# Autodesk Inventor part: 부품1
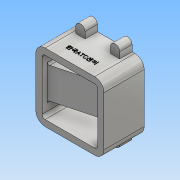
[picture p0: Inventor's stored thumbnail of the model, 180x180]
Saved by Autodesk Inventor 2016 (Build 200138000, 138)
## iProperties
Created: 2018-01
Part Number: 부품1
Material: 알루미늄 6061
Document SubType Name: Modeling
Designer: Administrator
Mass: 994.428 g
Surface Area: 845.509 cm^2
Volume: 368.307 cm^3
Density: 2.7 g/cm^3
Appearance: 알루미늄 - 평지
Author: Administrator
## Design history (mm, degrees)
sketch "스케치2"
  geometry: L1 (40, -55)-(-40, -55); L2 (-55, -40)-(-55, 40); L3 (-40, 55)-(40, 55); L4 (55, 40)-(55, -40); L5 (0, 55)-(0, -55); L6 (55, 0)-(-55, 0); A1 r 15 centre (40, -40) between (40, -55) and (55, -40); A2 r 15 centre (-40, -40) between (-55, -40) and (-40, -55); A3 r 15 centre (-40, 40) between (-40, 55) and (-55, 40); A4 r 15 centre (40, 40) between (55, 40) and (40, 55); 5 further points
  constraints: 12 end point, 8 point on circle, 8 tangent, 6 point on line, 5 midpoint, 4 centre point, 3 equal radius, 2 parallel, 1 coincident, 1 horizontal, 1 perpendicular
  dimensions: "d0" = 110 distance of point (-55, 55) point (55, 55); "d1" = 110 distance of point (-55, -55) point (-55, 55); "d2" = 15 radius of A1
extrude "돌출1" new body sketch "스케치2" distance "d3" = 65; taper "d4" = 0 deg
sketch "스케치3"
  geometry: L1 (40, 55)-(-40, 55) reference; L2 (-55, 40)-(-55, -40) reference; L3 (-35.5, 65)-(-35.5, 50.607); L4 (-35.5, 50.607)-(-20.5, 50.607); L5 (-20.5, 50.607)-(-20.5, 65); L6 (20.5, 65)-(20.5, 49.182); L7 (20.5, 49.182)-(35.5, 49.182); L8 (35.5, 49.182)-(35.5, 65); A1 r 7.5 centre (-28, 65) between (-20.5, 65) and (-35.5, 65); A2 r 7.5 centre (28, 65) between (35.5, 65) and (20.5, 65); 1 further point
  constraints: 12 end point, 4 point on circle, 2 centre point, 2 perpendicular, 2 tangent, 2 vertical
  dimensions: "d5" = 15 diameter of A1; "d6" = 15 diameter of A2; "d7" = 56 distance of A1.centre A2.centre; "d8" = 27 distance from line of A1.centre L2; "d9" = 10 distance from line of A1.centre L1; "d11" = 10 distance from line of L1 A2.centre; "d12" = 15 distance of L3.end L4.end; "d13" = 15 distance of L6.end L7.end; "d14" = 14.3934 distance of L4.end L5.end; "d15" = 14.3934 distance of L3.start L3.end; "d16" = 80 distance of L1.start L1.end (derived); "d17" = 15.81759 distance of L6.start L6.end; "d18" = 15.81759 distance of L7.end L8.end
extrude "돌출2" join sketch "스케치3" distance "d19" = 20; taper "d20" = 0 deg
sketch "스케치4"
  geometry: A1 r 7.5 centre (-28, 65) between (-20.5, 65) and (-35.5, 65) reference; 2 further points
  constraints: 1 coincident
hole "구멍1" sketch "스케치4" at (-28, 65) diameter "d21" = 3.242; stored, may be unused: countersink angle "d25" = 90 deg, drill point angle "d27" = 118 deg; dims "d22" = 8, "d23" = 4, "d24" = 2, "d26" = 11
node "작업 평면1"
sketch "스케치5"
  geometry: L1 (-15, 0)-(-15, 65) reference; L2 (95, 0)-(80, 0) reference; 2 further points
  constraints: 1 other
  dimensions: "d35" = 55 distance from line of L1 point (40, 20); "d36" = 20 distance from line of L2 point (40, 20)
feature "엠보싱1" sketch "스케치5" dims "d5" = 15, "d37" = 0.5, "d38" = 0
sketch "스케치6"
  geometry: L1 (55, -40)-(55, 40) reference; L2 (20.5, 55)-(-20.5, 55) reference; L3 (-55, 40)-(-55, -40) reference; L4 (-20.5, -55)-(20.5, -55) reference; L5 (-45, 45)-(45, 45); L6 (45, 54.142)-(45, -45); L7 (45, -45)-(-45, -45); L8 (-45, -45)-(-45, -25); L9 (-45, -25)-(35, -25); L10 (35, -25)-(35, 25); L11 (35, 25)-(-45, 25); L12 (-45, 25)-(-45, 45); A1 r 15 centre (40, -40) between (40, -55) and (55, -40) reference; A2 r 15 centre (40, 40) between (55, 40) and (40, 55) reference; A3 r 15 centre (-40, 40) between (-40, 55) and (-55, 40) reference; A4 r 15 centre (-40, -40) between (-55, -40) and (-40, -55) reference; 8 further points
  constraints: 16 end point, 6 perpendicular, 5 point on line, 4 point on circle, 1 horizontal, 1 parallel
  dimensions: "d39" = 10 distance between parallel lines of L7 L4; "d40" = 10 distance between parallel lines of L2 L5; "d41" = 30 distance between parallel lines of L11 L2; "d42" = 10 distance between parallel lines of L1 L6; "d43" = 20 distance between parallel lines of L1 L10; "d44" = 30 distance between parallel lines of L4 L9; "d45" = 10 distance from line of L3.end L8; "d46" = 10 distance between parallel lines of L3 L12
extrude "돌출3" cut sketch "스케치6" stored distance "d55" = 20; taper "d56" = 0 deg
sketch "스케치7"
  geometry: L1 (77, -65)-(-3, -65) reference; L2 (-3, -56.436)-(77, -35); L3 (97, -65)-(97, 0) reference; L4 (-13, -65)-(-13, 0) reference; L5 (-3, -56.436)-(-3, -72.207); L6 (77, -35)-(77, -72.207); L7 (77, -72.207)-(-3, -72.207); 3 further points
  constraints: 8 end point, 2 vertical, 1 perpendicular
  dimensions: "d59" = 30 distance from line of L1 L2.end; "d61" = 10 distance between parallel lines of L4 L5; "d62" = 105 deg angle of L2 L5; "d63" = 20 distance from line of L3 L6.end; "d65" = 37.20743 distance of L2.end L6.end
extrude "돌출4" cut sketch "스케치7" distance "d66" = 50; taper "d67" = 0 deg
sketch "스케치9"
  geometry: L1 (-40, 65)-(-55, 65) reference; L2 (-55, 65)-(30, 65); L3 (-40, 65)-(45, 65) reference; L4 (30, 65)-(30, 50); L5 (30, 50)-(25, 50); L6 (25, 50)-(25, 45); L7 (25, 45)-(-22, 45); L8 (-22, 45)-(-22, 49); L9 (-22, 49)-(-36, 49); L10 (-55, 0)-(-55, 65) reference; L11 (-36, 49)-(-36, 57.5); L12 (-36, 57.5)-(-55, 57.5); L13 (-55, 65)-(-55, 57.5); 2 further points
  constraints: 20 end point, 6 perpendicular, 2 point on line, 2 vertical, 1 collinear
  dimensions: "d78" = 7.5 distance between parallel lines of L1 L12; "d79" = 16 distance from line of L2 L9.end; "d80" = 20 distance from line of L2 L7.end; "d81" = 15 distance of L2.end L4.end; "d82" = 5 distance of L4.end L5.end; "d83" = 47 distance of L6.end L7.end; "d84" = 19 distance of L11.end L12.end; "d85" = 14 distance of L8.end L9.end
revolve "회전1" sketch "스케치9" stored, may be unused: angle "d86" = 90 deg
chamfer "모따기1" distance "d87" = 1; stored, may be unused: second distance "d88" = 2, angle "d89" = 45 deg
sketch "스케치10"
  geometry: L1 (-55, 0)-(-55, 65) reference; L2 (35, 30)-(-45, 8.564) reference; L3 (20, 31.157)-(-55, 11.061); L4 (-55, 11.061)-(-55, 29.061); L5 (-55, 29.061)-(-17, 39.243); L6 (-17, 39.243)-(-17, 54.361); L7 (-17, 54.361)-(20, 54.361); L8 (20, 54.361)-(20, 31.157); L9 (-22, 49)-(-22, 65) reference; 3 further points
  constraints: 12 end point, 2 parallel, 2 perpendicular, 2 point on line
  dimensions: "d90" = 5 distance between parallel lines of L2 L3; "d91" = 37 distance of L6.end L7.end; "d92" = 75 deg angle of L1 L5; "d93" = 18 distance of L3.end L4.end; "d94" = 5 distance between parallel lines of L9 L6; "d95" = 23.20373 distance of L7.end L3.start
extrude "돌출5" cut sketch "스케치10" stored distance "d96" = 30; taper "d97" = 0 deg
fillet "모깎기1" dims "d98" = 5
fillet "모깎기2" dims "d99" = 3
node "솔리드1"
mirror "대칭1"
pattern_linear "직사각형 패턴1" dims "d30" = 56
other parameters: "d34" = 39
